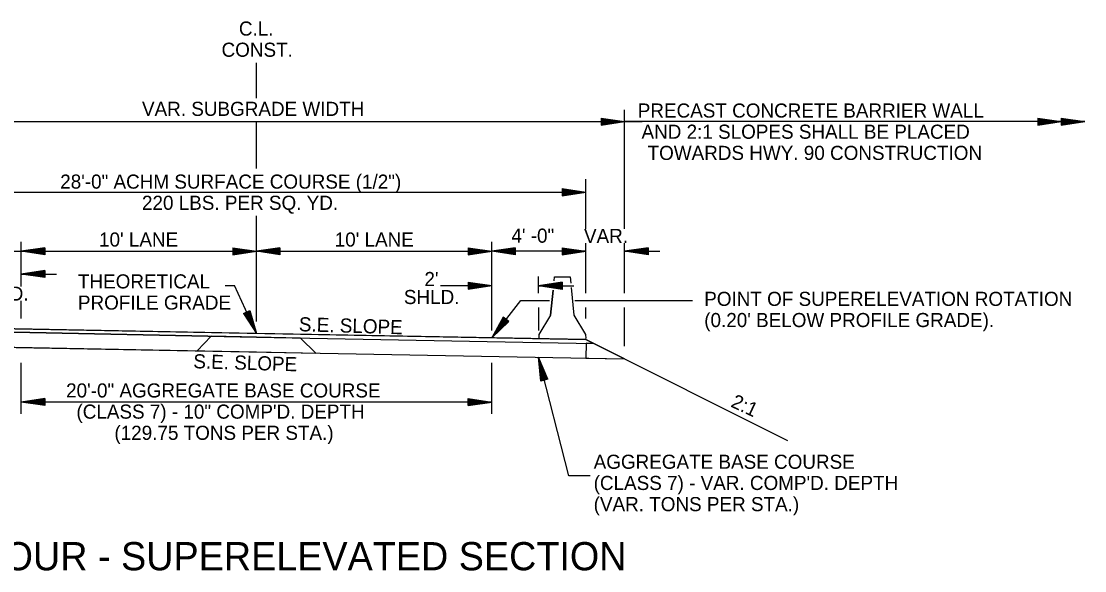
# Model space of a CAD drawing. Extents: x 138 to 3619, y -519 to 1449.
# Drawn here: x 2402.4 to 2854.5, y 302.4 to 535.9 of the extents above; entities that cross this region are included whole.
import ezdxf

# ---------------------------------------------------------------- set-up
doc = ezdxf.new("R2010")
doc.units = 0
for name, color, linetype in [('R_Annotation', 7, 'Continuous'), ('R_Barrier Wall', 7, 'Continuous'), ('R_Centerline', 7, 'Continuous'), ('R_Dimension', 7, 'Continuous')]:
    doc.layers.add(name, color=color, linetype=linetype)

msp = doc.modelspace()

# ---------------------------------------------------------------- linework, layer by layer
at = {"layer": 'R_Annotation'}
for p, q in [((2502.36, 401.55), (2360.91, 404.56)), ((2363.43, 405.81), (2642.36, 400.61)), ((2502.36, 401.55), (2645.75, 398.91)), ((2642.36, 400.61), (2728.13, 357.72)), ((2392.36, 397.37), (2658.85, 392.36))]:
    msp.add_line(p, q, dxfattribs=at)
msp.add_lwpolyline([(2502.36, 395.3), (2348.2, 398.2)], dxfattribs=at)
at = {"layer": 'R_Barrier Wall'}
for points in [[(2628.87, 425.61), (2629.04, 427.24), (2635.69, 427.24), (2635.97, 424.59)], [(2628.49, 421.61), (2627.37, 411.01), (2622.45, 402.68), (2622.37, 401.01)], [(2627.35, 411.01), (2628.48, 421.6)], [(2636.12, 422.71), (2637.36, 411.01), (2642.28, 402.68), (2642.36, 401.01)]]:
    msp.add_lwpolyline(points, dxfattribs=at)
at = {"layer": 'R_Centerline'}
for p, q in [((2502.36, 503.22), (2502.36, 518.22)), ((2502.36, 473.22), (2502.36, 493.22)), ((2502.36, 408.22), (2502.36, 453.22))]:
    msp.add_line(p, q, dxfattribs=at)
at = {"layer": 'R_Dimension'}
for p, q in [((2658.85, 447.62), (2658.85, 498.22)), ((2348.2, 493.22), (2666.4, 493.22)), ((2648.85, 494.72), (2658.85, 493.22)), ((2648.85, 494.72), (2648.85, 491.72)), ((2648.85, 494.47), (2657.18, 493.22)), ((2648.85, 494.21), (2655.46, 493.22)), ((2648.85, 493.96), (2653.8, 493.22)), ((2648.85, 493.7), (2652.1, 493.22)), ((2648.85, 493.45), (2650.43, 493.22)), ((2648.85, 491.72), (2658.85, 493.22)), ((2648.85, 492.73), (2652.1, 493.22)), ((2648.85, 492.22), (2655.46, 493.22)), ((2648.85, 491.97), (2657.18, 493.22)), ((2648.85, 492.47), (2653.8, 493.22)), ((2648.85, 492.98), (2650.43, 493.22)), ((2854.5, 493.22), (2658.85, 493.22)), ((2834.5, 494.72), (2844.5, 493.22)), ((2834.5, 494.72), (2834.5, 491.72)), ((2834.5, 494.47), (2842.83, 493.22)), ((2834.5, 494.21), (2841.11, 493.22)), ((2834.5, 493.96), (2839.44, 493.22)), ((2834.5, 493.7), (2837.75, 493.22)), ((2834.5, 493.45), (2836.08, 493.22)), ((2834.5, 491.72), (2844.5, 493.22)), ((2834.5, 492.73), (2837.75, 493.22)), ((2834.5, 492.22), (2841.11, 493.22)), ((2834.5, 491.97), (2842.83, 493.22)), ((2834.5, 492.47), (2839.44, 493.22)), ((2834.5, 492.98), (2836.08, 493.22)), ((2844.5, 494.72), (2854.5, 493.22)), ((2844.5, 494.72), (2844.5, 491.72)), ((2844.5, 494.47), (2852.83, 493.22)), ((2844.5, 494.21), (2851.11, 493.22)), ((2844.5, 493.96), (2849.45, 493.22)), ((2844.5, 493.7), (2847.75, 493.22)), ((2844.5, 493.45), (2846.08, 493.22)), ((2844.5, 491.72), (2854.5, 493.22)), ((2844.5, 492.73), (2847.75, 493.22)), ((2844.5, 492.22), (2851.11, 493.22)), ((2844.5, 491.97), (2852.83, 493.22)), ((2844.5, 492.47), (2849.45, 493.22)), ((2844.5, 492.98), (2846.08, 493.22)), ((2642.36, 447.62), (2642.36, 468.72)), ((2362.37, 463.23), (2642.36, 463.23)), ((2632.36, 464.72), (2642.36, 463.22)), ((2632.36, 464.72), (2632.36, 461.72)), ((2632.36, 464.47), (2640.69, 463.22)), ((2632.36, 464.22), (2638.97, 463.22)), ((2632.36, 463.97), (2637.3, 463.22)), ((2632.36, 463.71), (2635.61, 463.22)), ((2632.36, 463.46), (2633.94, 463.22)), ((2632.36, 461.72), (2642.36, 463.22)), ((2632.36, 462.73), (2635.61, 463.22)), ((2632.36, 462.23), (2638.97, 463.22)), ((2632.36, 461.97), (2640.69, 463.22)), ((2632.36, 462.48), (2637.3, 463.22)), ((2632.36, 462.99), (2633.94, 463.22)), ((2402.37, 423.11), (2402.37, 442.14)), ((2412.37, 439.64), (2402.37, 438.14)), ((2412.37, 439.39), (2404.04, 438.14)), ((2412.37, 439.13), (2405.76, 438.14)), ((2412.37, 438.88), (2407.42, 438.14)), ((2412.37, 438.62), (2409.12, 438.14)), ((2412.37, 439.64), (2412.37, 436.64)), ((2492.36, 439.64), (2502.36, 438.14)), ((2492.36, 439.64), (2492.36, 436.64)), ((2492.36, 439.39), (2500.69, 438.14)), ((2492.36, 439.13), (2498.97, 438.14)), ((2492.36, 438.88), (2497.3, 438.14)), ((2492.36, 438.62), (2495.61, 438.14)), ((2512.36, 439.64), (2502.36, 438.14)), ((2512.36, 439.39), (2504.03, 438.14)), ((2512.36, 439.13), (2505.75, 438.14)), ((2512.36, 438.88), (2507.41, 438.14)), ((2512.36, 438.62), (2509.11, 438.14)), ((2512.36, 439.64), (2512.36, 436.64)), ((2592.36, 439.64), (2602.36, 438.14)), ((2592.36, 439.64), (2592.36, 436.64)), ((2592.36, 439.39), (2600.69, 438.14)), ((2592.36, 439.13), (2598.97, 438.14)), ((2592.36, 438.88), (2597.3, 438.14)), ((2592.36, 438.62), (2595.61, 438.14)), ((2602.36, 404.5), (2602.36, 442.14)), ((2612.36, 439.64), (2602.36, 438.14)), ((2612.36, 439.39), (2604.03, 438.14)), ((2612.36, 439.13), (2605.75, 438.14)), ((2612.36, 438.88), (2607.41, 438.14)), ((2612.36, 438.62), (2609.11, 438.14)), ((2612.36, 439.64), (2612.36, 436.64)), ((2632.36, 439.64), (2642.36, 438.14)), ((2632.36, 439.64), (2632.36, 436.64)), ((2632.36, 439.39), (2640.69, 438.14)), ((2632.36, 439.13), (2638.97, 438.14)), ((2632.36, 438.88), (2637.3, 438.14)), ((2632.36, 438.62), (2635.61, 438.14)), ((2642.36, 420.24), (2642.36, 441.62)), ((2658.85, 420.24), (2658.85, 441.62)), ((2668.85, 439.64), (2658.85, 438.14)), ((2668.85, 439.39), (2660.52, 438.14)), ((2668.85, 439.13), (2662.24, 438.14)), ((2668.85, 438.88), (2663.91, 438.14)), ((2668.85, 438.62), (2665.6, 438.14)), ((2668.85, 439.64), (2668.85, 436.64)), ((2362.37, 438.14), (2602.36, 438.14)), ((2412.37, 436.64), (2402.37, 438.14)), ((2412.37, 436.89), (2404.04, 438.14)), ((2412.37, 437.14), (2405.76, 438.14)), ((2412.37, 437.39), (2407.42, 438.14)), ((2412.37, 437.65), (2409.12, 438.14)), ((2412.37, 438.37), (2410.79, 438.14)), ((2412.37, 437.9), (2410.79, 438.14)), ((2492.36, 438.37), (2493.94, 438.14)), ((2492.36, 436.64), (2502.36, 438.14)), ((2492.36, 437.65), (2495.61, 438.14)), ((2492.36, 437.14), (2498.97, 438.14)), ((2492.36, 436.89), (2500.69, 438.14)), ((2492.36, 437.39), (2497.3, 438.14)), ((2492.36, 437.9), (2493.94, 438.14)), ((2512.36, 436.64), (2502.36, 438.14)), ((2512.36, 436.89), (2504.03, 438.14)), ((2512.36, 437.14), (2505.75, 438.14)), ((2512.36, 437.39), (2507.41, 438.14)), ((2512.36, 437.65), (2509.11, 438.14)), ((2512.36, 438.37), (2510.78, 438.14)), ((2512.36, 437.9), (2510.78, 438.14)), ((2592.36, 438.37), (2593.94, 438.14)), ((2592.36, 436.64), (2602.36, 438.14)), ((2592.36, 437.65), (2595.61, 438.14)), ((2592.36, 437.14), (2598.97, 438.14)), ((2592.36, 436.89), (2600.69, 438.14)), ((2592.36, 437.39), (2597.3, 438.14)), ((2592.36, 437.9), (2593.94, 438.14)), ((2642.36, 438.14), (2602.36, 438.14)), ((2612.36, 436.64), (2602.36, 438.14)), ((2612.36, 436.89), (2604.03, 438.14)), ((2612.36, 437.14), (2605.75, 438.14)), ((2612.36, 437.39), (2607.41, 438.14)), ((2612.36, 437.65), (2609.11, 438.14)), ((2612.36, 438.37), (2610.78, 438.14)), ((2612.36, 437.9), (2610.78, 438.14)), ((2632.36, 438.37), (2633.94, 438.14)), ((2632.36, 436.64), (2642.36, 438.14)), ((2632.36, 437.65), (2635.61, 438.14)), ((2632.36, 437.14), (2638.97, 438.14)), ((2632.36, 436.89), (2640.69, 438.14)), ((2632.36, 437.39), (2637.3, 438.14)), ((2632.36, 437.9), (2633.94, 438.14)), ((2658.85, 438.14), (2673.85, 438.14)), ((2668.85, 436.64), (2658.85, 438.14)), ((2668.85, 436.89), (2660.52, 438.14)), ((2668.85, 437.14), (2662.24, 438.14)), ((2668.85, 437.39), (2663.91, 438.14)), ((2668.85, 437.65), (2665.6, 438.14)), ((2668.85, 438.37), (2667.27, 438.14)), ((2668.85, 437.9), (2667.27, 438.14)), ((2412.37, 429.9), (2402.37, 428.4)), ((2412.37, 429.65), (2404.04, 428.4)), ((2412.37, 429.9), (2412.37, 426.9)), ((2412.37, 426.9), (2402.37, 428.4)), ((2402.37, 428.4), (2417.37, 428.4)), ((2412.37, 427.15), (2404.04, 428.4)), ((2412.37, 429.39), (2405.76, 428.4)), ((2412.37, 427.4), (2405.76, 428.4)), ((2412.37, 429.14), (2407.42, 428.4)), ((2412.37, 427.65), (2407.42, 428.4)), ((2412.37, 428.88), (2409.12, 428.4)), ((2412.37, 427.91), (2409.12, 428.4)), ((2412.37, 428.63), (2410.79, 428.4)), ((2412.37, 428.16), (2410.79, 428.4)), ((2592.36, 425.05), (2602.36, 423.55)), ((2592.36, 425.05), (2592.36, 422.05)), ((2622.34, 420.24), (2622.34, 427.44)), ((2489.12, 423.55), (2493.08, 423.55)), ((2580.62, 423.55), (2602.36, 423.55)), ((2592.36, 424.8), (2600.69, 423.55)), ((2592.36, 424.55), (2598.97, 423.55)), ((2592.36, 424.3), (2597.3, 423.55)), ((2592.36, 424.04), (2595.61, 423.55)), ((2592.36, 423.79), (2593.94, 423.55)), ((2592.36, 422.05), (2602.36, 423.55)), ((2592.36, 423.06), (2595.61, 423.55)), ((2592.36, 422.56), (2598.97, 423.55)), ((2592.36, 422.3), (2600.69, 423.55)), ((2592.36, 422.81), (2597.3, 423.55)), ((2592.36, 423.32), (2593.94, 423.55)), ((2632.34, 424.92), (2622.34, 423.42)), ((2632.34, 421.92), (2622.34, 423.42)), ((2622.34, 423.42), (2637.34, 423.42)), ((2632.34, 424.67), (2624.01, 423.42)), ((2632.34, 422.17), (2624.01, 423.42)), ((2632.34, 424.42), (2625.73, 423.42)), ((2632.34, 422.43), (2625.73, 423.42)), ((2632.34, 424.17), (2627.39, 423.42)), ((2632.34, 422.68), (2627.39, 423.42)), ((2632.34, 423.91), (2629.09, 423.42)), ((2632.34, 422.93), (2629.09, 423.42)), ((2632.34, 423.66), (2630.76, 423.42)), ((2632.34, 423.19), (2630.76, 423.42)), ((2632.34, 424.92), (2632.34, 421.92)), ((2402.37, 409.57), (2402.37, 417.11)), ((2496.84, 411.69), (2499.57, 412.94)), ((2496.84, 411.69), (2502.36, 403.22)), ((2497.07, 411.8), (2501.66, 404.74)), ((2497.3, 411.9), (2500.95, 406.3)), ((2497.52, 412.01), (2500.26, 407.82)), ((2497.76, 412.11), (2499.55, 409.36)), ((2497.99, 412.22), (2498.86, 410.88)), ((2498.42, 412.41), (2498.86, 410.88)), ((2498.65, 412.52), (2499.55, 409.36)), ((2498.88, 412.63), (2500.26, 407.82)), ((2499.11, 412.73), (2500.95, 406.3)), ((2499.34, 412.83), (2501.66, 404.74)), ((2499.57, 412.94), (2502.36, 403.22)), ((2622.36, 404.5), (2622.35, 414.24)), ((2642.36, 409.56), (2642.36, 414.24)), ((2658.85, 397.76), (2658.85, 414.24)), ((2607.3, 410.15), (2602.36, 401.33)), ((2609.67, 408.31), (2602.36, 401.33)), ((2607.5, 410), (2603.38, 402.65)), ((2609.47, 408.47), (2603.38, 402.65)), ((2607.7, 409.84), (2604.43, 404.01)), ((2609.27, 408.62), (2604.43, 404.01)), ((2607.9, 409.69), (2605.45, 405.32)), ((2609.07, 408.77), (2605.45, 405.32)), ((2608.1, 409.53), (2606.49, 406.66)), ((2608.87, 408.93), (2606.49, 406.66)), ((2609.67, 408.31), (2607.3, 410.15)), ((2608.3, 409.38), (2607.52, 407.98)), ((2608.67, 409.09), (2607.52, 407.98)), ((2362.09, 404.48), (2502.36, 401.55)), ((2502.36, 403.22), (2363.43, 405.81)), ((2642.36, 400.61), (2502.36, 403.22)), ((2483.14, 402.02), (2477.18, 395.8)), ((2502.36, 401.58), (2483.14, 402.02)), ((2521.06, 401.21), (2502.36, 401.58)), ((2502.36, 401.55), (2645.75, 398.91)), ((2527.58, 394.83), (2521.06, 401.21)), ((2645.75, 398.91), (2642.36, 400.61)), ((2642.5, 398.99), (2642.44, 392.68)), ((2645.75, 398.91), (2642.5, 398.99)), ((2658.81, 392.38), (2645.75, 398.91)), ((2477.18, 395.8), (2502.36, 395.33)), ((2502.36, 395.33), (2527.58, 394.83)), ((2402.37, 369.01), (2402.37, 390.72)), ((2602.36, 369.01), (2602.36, 390.72)), ((2626.2, 383.73), (2622.26, 393.04)), ((2623.3, 382.98), (2622.26, 393.04)), ((2625.96, 383.66), (2622.67, 391.42)), ((2623.54, 383.04), (2622.67, 391.42)), ((2623.78, 383.1), (2623.1, 389.75)), ((2625.71, 383.6), (2623.1, 389.75)), ((2642.44, 392.68), (2658.81, 392.38)), ((2625.47, 383.54), (2623.52, 388.14)), ((2624.03, 383.17), (2623.52, 388.14)), ((2624.27, 383.23), (2623.94, 386.5)), ((2625.22, 383.47), (2623.94, 386.5)), ((2624.52, 383.29), (2624.36, 384.88)), ((2624.98, 383.41), (2624.36, 384.88)), ((2626.2, 383.73), (2623.3, 382.98)), ((2412.37, 375.51), (2402.37, 374.01)), ((2412.37, 375.51), (2412.37, 372.51)), ((2592.36, 375.51), (2602.36, 374.01)), ((2592.36, 372.51), (2592.36, 375.51)), ((2602.36, 374.01), (2402.37, 374.01)), ((2412.37, 372.51), (2402.37, 374.01)), ((2412.37, 375.26), (2404.04, 374.01)), ((2412.37, 372.76), (2404.04, 374.01)), ((2412.37, 375.01), (2405.76, 374.01)), ((2412.37, 373.02), (2405.76, 374.01)), ((2412.37, 374.76), (2407.42, 374.01)), ((2412.37, 373.27), (2407.42, 374.01)), ((2412.37, 374.5), (2409.12, 374.01)), ((2412.37, 373.52), (2409.12, 374.01)), ((2412.37, 374.25), (2410.79, 374.01)), ((2412.37, 373.78), (2410.79, 374.01)), ((2592.36, 375.26), (2600.69, 374.01)), ((2592.36, 375.01), (2598.97, 374.01)), ((2592.36, 374.76), (2597.3, 374.01)), ((2592.36, 374.5), (2595.61, 374.01)), ((2592.36, 374.25), (2593.94, 374.01)), ((2592.36, 372.51), (2602.36, 374.01)), ((2592.36, 373.53), (2595.61, 374.01)), ((2592.36, 373.02), (2598.97, 374.01)), ((2592.36, 372.76), (2600.69, 374.01)), ((2592.36, 373.27), (2597.3, 374.01)), ((2592.36, 373.78), (2593.94, 374.01))]:
    msp.add_line(p, q, dxfattribs=at)
for points in [[(2502.36, 403.22), (2493.08, 423.55)], [(2602.36, 401.33), (2614.7, 417.24), (2627.01, 417.24)], [(2637.7, 417.24), (2687.71, 417.24)], [(2644.22, 342.68), (2635.23, 342.68), (2622.26, 393.05)]]:
    msp.add_lwpolyline(points, dxfattribs=at)

# ---------------------------------------------------------------- texts
at = {"layer": 'R_Annotation'}
for s, height, p in [('C.L.', 6, (2494.89, 529.76)), ('CONST.', 6, (2487.52, 520.76)), ('VAR. SUBGRADE WIDTH', 6, (2453.69, 495.64)), ('PRECAST CONCRETE BARRIER WALL', 6, (2664.47, 494.92)), ('AND 2:1 SLOPES SHALL BE PLACED', 6, (2666.06, 485.92)), ('TOWARDS HWY. 90 CONSTRUCTION', 6, (2668.65, 476.92)), ('28\'-0" ACHM SURFACE COURSE (1/2")', 6, (2418.92, 464.72)), ('220 LBS. PER SQ. YD. ', 6, (2453.69, 455.72)), ('4\' -0"', 6, (2610.75, 441.74)), ('VAR.', 6, (2641.61, 441.62)), ("10' LANE", 6, (2435.43, 440.11)), ("10' LANE", 6, (2535.63, 440.11)), ('THEORETICAL', 6, (2426.46, 422.31)), ("2'", 6, (2573.77, 423.31)), ('SHLD.', 6, (2381.84, 417.11)), ('SHLD.', 6, (2565.03, 415.68)), ('POINT OF SUPERELEVATION ROTATION ', 6, (2692.73, 414.89)), ('PROFILE GRADE', 6, (2426.46, 413.31)), ("(0.20' BELOW PROFILE GRADE).", 6, (2692.73, 405.89)), ('20\'-0" AGGREGATE BASE COURSE', 6, (2421.43, 375.97)), ('(CLASS 7) - 10" COMP\'D. DEPTH', 6, (2425.82, 366.97)), ('(129.75 TONS PER STA.)', 6, (2441.97, 357.97)), ('AGGREGATE BASE COURSE', 6, (2645.72, 345.66)), ("(CLASS 7) - VAR. COMP'D. DEPTH", 6, (2645.72, 336.66)), ('(VAR. TONS PER STA.)', 6, (2645.72, 327.66)), ('TEMP. DETOUR - SUPERELEVATED SECTION', 12, (2309.28, 302.53))]:
    msp.add_text(s, height=height, dxfattribs=at).set_placement(p)
for s, rotation, p in [('S.E. SLOPE', 358.2609, (2520.32, 404.15)), ('S.E. SLOPE', 358.2609, (2475.45, 388.42)), ('2:1', 335.0374, (2703.64, 372.2))]:
    msp.add_text(s, height=6, rotation=rotation, dxfattribs=at).set_placement(p)

doc.saveas('drawing.dxf')
